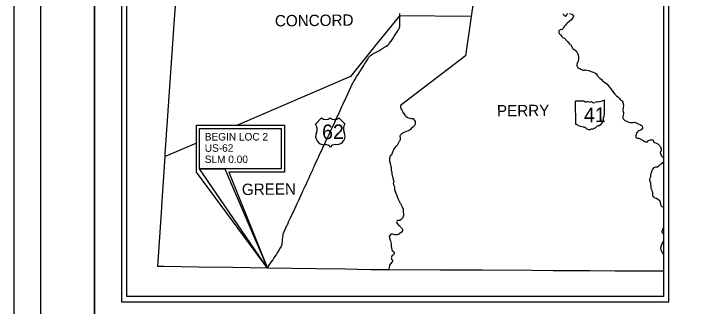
# Model space of a CAD drawing. Extents: x -12 to 164, y -741 to 24.
# Drawn here: x 0 to 12.93, y 8.83 to 14.26 of the extents above; entities that cross this region are included whole.
import ezdxf

# ---------------------------------------------------------------- set-up
doc = ezdxf.new("R2010")
doc.units = 0
for name, color, linetype in [('Default', 7, 'Continuous'), ('PM_P_Channelizing_Line', 7, 'Continuous'), ('PM_P_Crosswalk', 7, 'Continuous'), ('PM_P_Parking_Lot_Stall', 7, 'Continuous'), ('PM_P_Stop_Line', 7, 'Continuous'), ('PM_X_Channelizing_Line', 7, 'Continuous'), ('SH_Border', 7, 'Continuous'), ('SH_Cut_Line', 7, 'Continuous'), ('SH_Data', 7, 'Continuous'), ('SH_Text', 7, 'Continuous')]:
    doc.layers.add(name, color=color, linetype=linetype)

msp = doc.modelspace()

# ---------------------------------------------------------------- linework, layer by layer
at = {"layer": 'PM_P_Channelizing_Line'}
for points in [[(8.575, 14.773), (8.496, 14.218), (7.163, 14.227), (6.702, 13.656), (6.252, 13.102), (4.155, 12.192)], [(3.39, 11.861), (2.81, 11.609), (2.813, 11.659), (2.856, 12.282), (2.984, 14.169), (3.012, 14.574)], [(10.32, 14.274), (10.368, 14.258), (10.387, 14.246), (10.394, 14.237), (10.397, 14.23), (10.397, 14.22), (10.383, 14.193), (10.35, 14.151), (10.303, 14.109), (10.285, 14.096), (10.269, 14.078), (10.245, 14.054), (10.23, 14.036), (10.202, 13.99), (10.193, 13.981), (10.184, 13.975), (10.174, 13.972), (10.15, 13.969), (10.141, 13.964), (10.133, 13.957), (10.127, 13.948), (10.124, 13.939), (10.126, 13.931), (10.125, 13.921), (10.133, 13.903), (10.139, 13.895), (10.154, 13.878), (10.172, 13.853), (10.198, 13.825), (10.209, 13.817), (10.226, 13.813), (10.234, 13.808), (10.243, 13.8), (10.25, 13.791), (10.256, 13.782), (10.282, 13.757), (10.289, 13.748), (10.294, 13.74), (10.312, 13.724), (10.32, 13.707), (10.327, 13.698), (10.345, 13.692), (10.351, 13.682), (10.357, 13.656), (10.375, 13.631), (10.384, 13.622), (10.409, 13.6), (10.426, 13.587), (10.459, 13.553), (10.463, 13.545), (10.469, 13.536), (10.483, 13.504), (10.486, 13.495), (10.49, 13.477), (10.488, 13.431), (10.481, 13.393), (10.477, 13.368), (10.474, 13.36), (10.464, 13.341), (10.459, 13.324), (10.459, 13.316), (10.46, 13.299), (10.463, 13.29), (10.48, 13.264), (10.488, 13.257), (10.515, 13.246), (10.535, 13.237), (10.556, 13.225), (10.564, 13.222), (10.584, 13.219), (10.601, 13.22), (10.61, 13.223), (10.618, 13.223), (10.644, 13.219), (10.68, 13.211), (10.725, 13.195), (10.744, 13.186), (10.762, 13.181), (10.791, 13.17), (10.81, 13.157), (10.818, 13.149), (10.842, 13.112), (10.868, 13.085), (10.875, 13.076), (10.883, 13.069), (10.91, 13.049), (10.936, 13.022), (10.956, 13.007), (10.963, 12.999), (11.007, 12.967), (11.025, 12.951), (11.033, 12.943), (11.044, 12.925), (11.06, 12.907), (11.076, 12.891), (11.104, 12.849), (11.167, 12.772), (11.192, 12.746), (11.229, 12.716), (11.244, 12.698), (11.262, 12.673), (11.27, 12.664), (11.278, 12.659), (11.295, 12.655), (11.303, 12.648), (11.306, 12.641), (11.31, 12.625), (11.316, 12.616), (11.319, 12.608), (11.321, 12.599), (11.323, 12.555), (11.319, 12.529), (11.314, 12.476), (11.318, 12.449), (11.324, 12.432), (11.327, 12.415), (11.316, 12.345), (11.313, 12.335), (11.313, 12.327), (11.32, 12.31), (11.326, 12.303), (11.351, 12.283), (11.368, 12.272), (11.405, 12.258), (11.424, 12.253), (11.45, 12.247), (11.468, 12.244), (11.493, 12.243), (11.509, 12.244), (11.534, 12.249), (11.55, 12.245), (11.64, 12.203), (11.657, 12.191), (11.666, 12.184), (11.672, 12.175), (11.676, 12.166), (11.679, 12.149), (11.678, 12.141), (11.669, 12.123), (11.664, 12.115), (11.656, 12.106), (11.629, 12.098), (11.603, 12.086), (11.594, 12.079), (11.58, 12.062), (11.569, 12.043), (11.558, 12.018), (11.555, 12.01), (11.552, 11.993), (11.553, 11.977), (11.556, 11.969), (11.565, 11.961), (11.586, 11.954), (11.612, 11.951), (11.621, 11.947), (11.689, 11.912), (11.714, 11.892), (11.722, 11.888), (11.742, 11.882), (11.75, 11.881), (11.766, 11.882), (11.774, 11.886), (11.782, 11.903), (11.79, 11.91), (11.822, 11.92), (11.847, 11.921), (11.864, 11.92), (11.877, 11.914), (11.88, 11.905), (11.88, 11.897), (11.884, 11.889), (11.891, 11.879), (11.9, 11.874), (11.934, 11.862), (11.961, 11.847), (11.979, 11.83), (11.994, 11.814), (12.001, 11.806), (12.01, 11.789), (12.017, 11.772), (12.023, 11.754), (12.027, 11.729), (12.01, 11.701), (12.008, 11.693), (12.008, 11.684), (12.02, 11.648), (12.027, 11.631), (12.033, 11.622), (12.041, 11.614), (12.05, 11.608), (12.056, 11.601), (12.061, 11.593), (12.066, 11.581)], [(10.203, 14.265), (10.207, 14.255), (10.215, 14.243), (10.224, 14.234), (10.233, 14.226), (10.245, 14.22), (10.254, 14.221), (10.263, 14.23), (10.27, 14.247), (10.275, 14.255), (10.283, 14.264), (10.293, 14.273)], [(8.496, 14.218), (8.465, 13.997), (8.393, 13.483), (7.185, 12.558), (7.183, 12.543), (7.185, 12.526), (7.189, 12.509), (7.196, 12.491), (7.208, 12.471), (7.226, 12.434), (7.236, 12.417), (7.264, 12.381), (7.279, 12.364), (7.305, 12.342), (7.315, 12.337), (7.356, 12.325), (7.382, 12.32), (7.4, 12.319), (7.413, 12.316), (7.421, 12.311), (7.437, 12.293), (7.443, 12.284), (7.452, 12.264), (7.457, 12.244), (7.456, 12.227), (7.453, 12.21), (7.45, 12.201), (7.444, 12.191), (7.436, 12.183), (7.409, 12.16), (7.383, 12.132), (7.366, 12.111), (7.35, 12.099), (7.325, 12.089), (7.264, 12.066), (7.245, 12.055), (7.206, 12.035), (7.196, 12.028), (7.187, 12.019), (7.18, 12.01), (7.175, 12.001), (7.173, 11.992), (7.176, 11.956), (7.176, 11.923), (7.166, 11.897), (7.159, 11.889), (7.135, 11.844), (7.123, 11.816), (7.116, 11.807), (7.098, 11.799), (7.09, 11.793), (7.076, 11.775), (7.071, 11.767), (7.059, 11.745), (7.055, 11.734), (7.049, 11.724), (7.02, 11.656), (7.008, 11.639), (6.999, 11.63), (6.993, 11.62), (6.986, 11.601), (6.981, 11.565), (6.981, 11.53), (6.994, 11.464), (7.004, 11.423), (7.007, 11.404), (7.009, 11.37), (7.011, 11.361), (7.02, 11.309), (7.019, 11.284), (7.027, 11.257), (7.045, 11.199), (7.049, 11.179), (7.057, 11.152), (7.058, 11.143), (7.057, 11.134), (7.052, 11.125), (7.048, 11.116), (7.052, 11.092), (7.054, 11.084), (7.064, 11.057), (7.068, 11.049), (7.071, 11.04), (7.073, 11.023), (7.07, 11.005), (7.071, 10.997), (7.082, 10.963), (7.098, 10.929), (7.116, 10.886), (7.128, 10.849), (7.141, 10.819), (7.157, 10.783), (7.178, 10.743), (7.181, 10.735), (7.211, 10.676), (7.229, 10.633), (7.232, 10.615), (7.229, 10.587), (7.229, 10.577), (7.236, 10.544), (7.237, 10.525), (7.233, 10.497), (7.226, 10.479), (7.218, 10.465), (7.212, 10.457), (7.194, 10.438), (7.176, 10.426), (7.167, 10.423), (7.159, 10.421), (7.132, 10.419), (7.123, 10.414), (7.114, 10.406), (7.11, 10.396), (7.112, 10.38), (7.115, 10.372), (7.123, 10.362), (7.154, 10.328), (7.162, 10.32), (7.189, 10.299), (7.204, 10.283), (7.21, 10.275), (7.215, 10.267), (7.219, 10.257), (7.221, 10.237), (7.219, 10.227), (7.2, 10.201), (7.147, 10.158), (7.12, 10.152), (7.104, 10.152), (7.077, 10.154), (7.058, 10.159), (7.032, 10.168), (7.024, 10.169), (7.015, 10.168), (7.006, 10.164), (6.998, 10.158), (6.976, 10.131), (6.974, 10.123), (6.981, 10.097), (6.989, 10.062), (6.992, 10.054), (6.998, 10.045), (7.005, 10.019), (7.01, 9.983), (7.011, 9.936), (7.022, 9.881), (7.028, 9.865), (7.056, 9.836), (7.063, 9.818), (7.065, 9.809), (7.064, 9.801), (7.059, 9.793), (7.05, 9.784), (7.025, 9.767), (7.016, 9.75), (7.013, 9.737), (7.012, 9.728), (7.014, 9.712), (7.017, 9.703), (7.034, 9.677), (7.036, 9.667), (7.033, 9.659), (7.026, 9.649), (6.988, 9.606), (6.979, 9.588), (6.975, 9.577), (6.969, 9.55), (6.967, 9.513), (6.963, 9.503), (6.696, 9.505), (6.633, 9.506), (6.159, 9.513), (5.611, 9.521), (4.713, 9.535), (4.066, 9.545), (3.429, 9.554), (2.784, 9.564), (2.671, 9.566), (2.746, 10.664), (2.747, 10.685), (2.81, 11.609)], [(12.066, 10.665), (12.062, 10.667), (12.045, 10.676), (12.036, 10.683), (12.028, 10.692), (12.023, 10.701), (12.018, 10.726), (12.016, 10.75), (12.014, 10.759), (12.007, 10.777), (12.001, 10.786), (11.984, 10.801), (11.94, 10.829), (11.912, 10.837), (11.904, 10.84), (11.894, 10.846), (11.885, 10.855), (11.876, 10.872), (11.872, 10.879), (11.868, 10.907), (11.869, 10.925), (11.868, 10.942), (11.866, 10.952), (11.86, 10.972), (11.849, 10.997), (11.844, 11.005), (11.842, 11.014), (11.838, 11.04), (11.836, 11.107), (11.835, 11.115), (11.825, 11.132), (11.819, 11.151), (11.816, 11.168), (11.817, 11.184), (11.823, 11.21), (11.828, 11.226), (11.833, 11.235), (11.835, 11.243), (11.836, 11.26), (11.842, 11.297), (11.861, 11.352), (11.867, 11.365), (11.897, 11.404), (11.905, 11.411), (11.924, 11.417), (11.949, 11.419), (11.959, 11.422), (11.975, 11.432), (12.001, 11.455), (12.042, 11.48), (12.059, 11.497), (12.064, 11.505), (12.066, 11.508)], [(12.066, 10.173), (12.052, 10.185), (12.048, 10.194), (12.045, 10.203), (12.045, 10.219), (12.047, 10.227), (12.054, 10.254), (12.061, 10.275), (12.066, 10.284)], [(12.066, 9.796), (12.065, 9.796), (12.043, 9.83), (12.031, 9.856), (12.025, 9.872), (12.019, 9.899), (12.019, 9.915), (12.03, 9.958), (12.042, 9.992), (12.066, 10.045)], [(12.066, 9.477), (11.932, 9.477), (11.467, 9.48), (11.173, 9.481), (10.697, 9.484), (10.017, 9.487), (9.629, 9.489), (8.701, 9.494), (7.924, 9.498), (6.963, 9.503)]]:
    msp.add_lwpolyline(points, dxfattribs=at)
at = {"layer": 'PM_P_Crosswalk'}
msp.add_lwpolyline([(4.71, 9.536), (4.715, 9.546), (4.724, 9.559), (4.755, 9.606), (4.786, 9.651), (4.809, 9.685), (4.831, 9.717), (4.848, 9.742), (4.871, 9.776), (4.885, 9.798), (4.893, 9.811), (4.908, 9.837), (4.939, 9.891), (4.963, 9.933), (4.972, 9.949), (4.976, 9.958), (4.978, 9.963), (4.98, 9.968), (4.982, 9.976), (4.983, 9.983), (4.985, 9.993), (4.99, 10.042), (4.992, 10.065), (4.996, 10.103), (5, 10.144), (5.001, 10.157), (5.002, 10.165), (5.004, 10.175), (5.006, 10.182), (5.009, 10.189), (5.013, 10.199), (5.018, 10.21), (5.031, 10.238), (5.053, 10.285), (5.079, 10.34), (5.086, 10.354), (5.104, 10.394), (5.139, 10.468), (5.184, 10.564), (5.199, 10.596), (5.221, 10.643), (5.229, 10.661), (5.243, 10.692), (5.257, 10.722), (5.271, 10.752), (5.294, 10.801), (5.318, 10.855), (5.333, 10.888), (5.342, 10.907), (5.363, 10.953), (5.386, 11.002), (5.395, 11.023), (5.407, 11.049), (5.427, 11.093), (5.449, 11.14), (5.483, 11.215), (5.493, 11.236), (5.507, 11.266), (5.541, 11.341), (5.557, 11.376), (5.568, 11.402), (5.578, 11.423), (5.598, 11.467), (5.648, 11.574), (5.664, 11.609), (5.672, 11.628), (5.698, 11.684), (5.725, 11.742), (5.738, 11.77), (5.753, 11.803), (5.775, 11.85), (5.804, 11.913), (5.819, 11.945), (5.854, 12.022), (5.877, 12.071), (5.888, 12.094), (5.918, 12.16), (5.961, 12.253), (5.988, 12.311), (6.008, 12.353), (6.022, 12.383), (6.04, 12.423), (6.08, 12.509), (6.094, 12.54), (6.101, 12.554), (6.116, 12.589), (6.138, 12.635), (6.152, 12.665), (6.178, 12.721), (6.209, 12.789), (6.235, 12.845), (6.262, 12.903), (6.28, 12.943), (6.29, 12.964), (6.299, 12.982), (6.305, 12.993), (6.313, 13.007), (6.333, 13.039), (6.374, 13.105), (6.393, 13.135), (6.426, 13.188), (6.437, 13.205), (6.446, 13.22), (6.488, 13.288), (6.514, 13.329), (6.532, 13.357), (6.539, 13.368), (6.562, 13.405), (6.579, 13.434), (6.59, 13.451), (6.597, 13.462), (6.602, 13.468), (6.602, 13.468), (6.607, 13.474), (6.613, 13.479), (6.618, 13.484), (6.625, 13.489), (6.631, 13.493), (6.642, 13.5), (6.664, 13.513), (6.708, 13.539), (6.741, 13.558), (6.777, 13.579), (6.856, 13.626), (6.911, 13.659), (6.936, 13.674), (6.944, 13.679), (6.95, 13.684), (6.954, 13.687), (6.96, 13.693), (6.965, 13.698), (6.968, 13.702), (6.974, 13.711), (7.007, 13.76), (7.044, 13.816), (7.077, 13.868), (7.118, 13.93), (7.147, 13.973), (7.154, 13.984), (7.157, 13.99), (7.161, 13.997), (7.163, 14.005), (7.164, 14.007), (7.165, 14.01), (7.166, 14.015), (7.166, 14.016), (7.167, 14.02), (7.167, 14.027), (7.168, 14.048), (7.167, 14.066), (7.167, 14.094), (7.168, 14.138), (7.168, 14.169), (7.168, 14.226), (7.168, 14.236), (7.169, 14.259), (7.17, 14.274)], dxfattribs=at)
at = {"layer": 'PM_P_Parking_Lot_Stall'}
for p, q in [((10.428, 12.631), (10.432, 12.218)), ((10.593, 12.64), (10.434, 12.638)), ((10.975, 12.437), (10.973, 12.654)), ((10.975, 12.437), (10.975, 12.437))]:
    msp.add_line(p, q, dxfattribs=at)
for centre, radius, start, end in [((10.435, 12.632), 0.00631, 98.6686, 188.6686), ((10.631, 12.688), 0.0612, 232.1581, 271.6504), ((10.654, 12.408), 0.22, 81.0252, 95.5268), ((10.701, 12.637), 0.0177, 220.3306, 297.6409), ((10.728, 12.589), 0.0367, 55.0052, 119.6797), ((10.775, 12.655), 0.0442, 234.3948, 295.3667), ((10.854, 12.516), 0.116, 97.8847, 121.3074), ((10.774, 13.205), 0.578, 276.383, 289.445), ((10.967, 12.654), 0.00607, 352.4006, 98.2765), ((10.974, 12.421), 0.00939, 108.4825, 210.8755), ((10.969, 12.436), 0.00649, 290.1424, 8.2727), ((10.814, 12.318), 0.145, 292.8474, 9.5244), ((10.998, 12.347), 0.041, 137.345, 187.4681), ((10.914, 12.394), 0.0563, 340.5715, 24.1881), ((10.439, 12.217), 0.00637, 172.4969, 258.8452), ((10.439, 12.259), 0.0486, 267.8775, 281.1424), ((10.45, 12.194), 0.0175, 30.2869, 93.8103), ((10.667, 12.568), 0.417, 240.9515, 257.737), ((10.548, 12.033), 0.131, 47.7227, 76.3745), ((10.877, 12.106), 0.0791, 94.9417, 143.1153), ((10.688, 12.194), 0.0828, 231.2389, 286.8304), ((10.737, 12.052), 0.0681, 86.2337, 111.7485), ((10.742, 12.164), 0.0441, 269.3156, 316.0878), ((10.782, 12.124), 0.0124, 66.2903, 133.187), ((10.776, 12.181), 0.0467, 283.4117, 323.8157)]:
    msp.add_arc(centre, radius, start, end, dxfattribs=at)
at = {"layer": 'PM_P_Stop_Line'}
for p, q in [((5.717, 12.33), (5.605, 12.216)), ((6.15, 12.221), (6.035, 12.333)), ((5.767, 11.831), (5.79, 11.832)), ((5.972, 11.833), (5.994, 11.834))]:
    msp.add_line(p, q, dxfattribs=at)
for centre, radius, start, end in [((5.796, 12.412), 0.114, 226.1115, 314.9656), ((5.955, 12.414), 0.114, 226.1115, 314.9656), ((5.475, 12.123), 0.159, 335.0857, 35.5395), ((6.281, 12.131), 0.159, 145.5376, 205.9914), ((5.764, 11.99), 0.159, 155.3705, 271.1768), ((5.995, 11.992), 0.159, 269.9003, 25.7066), ((5.791, 11.718), 0.114, 37.4084, 90.5385), ((5.973, 11.72), 0.114, 90.5385, 143.6686)]:
    msp.add_arc(centre, radius, start, end, dxfattribs=at)
at = {"layer": 'SH_Border'}
for points in [[(0.5, 21.5), (1.5, 21.5), (1.5, 0.5), (0.5, 0.5)], [(1.5, 21.5), (33.5, 21.5), (33.5, 0.5), (1.5, 0.5)]]:
    msp.add_lwpolyline(points, close=True, dxfattribs=at)
at = {"layer": 'SH_Cut_Line'}
msp.add_lwpolyline([(0, 0), (34, 0), (34, 22), (0, 22)], close=True, dxfattribs=at)
at = {"layer": 'SH_Data'}
msp.add_line((2.1, 14.1), (2.1, 14.1), dxfattribs=at)
for points in [[(6.977, 21), (2, 21), (2, 8.906), (12.166, 8.906), (12.166, 18.656)], [(12.066, 18.656), (12.066, 9.006), (2.1, 9.006), (2.1, 20.9), (6.977, 20.9)]]:
    msp.add_lwpolyline(points, dxfattribs=at)
for points in [[(3.45, 12.132), (4.967, 12.132), (4.967, 11.381), (3.45, 11.381)], [(3.921, 11.381), (4.71, 9.536), (3.45, 11.381)]]:
    msp.add_lwpolyline(points, close=True, dxfattribs=at)
at = {"layer": 'SH_Text'}
for p, q in [((3.39, 12.192), (5.027, 12.192)), ((3.39, 11.321), (3.39, 12.192)), ((5.027, 12.192), (5.027, 11.321)), ((4.71, 9.536), (3.39, 11.321)), ((5.027, 11.321), (3.994, 11.321)), ((3.994, 11.321), (4.71, 9.536))]:
    msp.add_line(p, q, dxfattribs=at)

# ---------------------------------------------------------------- texts
at = {"layer": 'Default'}
for s, p in [('BEGIN LOC 2', (3.546, 11.909)), ('US-62', (3.546, 11.699)), ('SLM 0.00', (3.546, 11.489))]:
    msp.add_text(s, height=0.14, dxfattribs=at).set_placement(p)
at = {"layer": 'PM_P_Parking_Lot_Stall'}
msp.add_text('41', height=0.2724, rotation=0.5385, dxfattribs=at).set_placement((10.591, 12.248))
at = {"layer": 'PM_P_Stop_Line'}
msp.add_text('62', height=0.2724, rotation=0.5385, dxfattribs=at).set_placement((5.726, 11.933))
at = {"layer": 'PM_X_Channelizing_Line'}
for s, p in [('CONCORD', (4.85, 14.031)), ('PERRY', (8.975, 12.356)), ('GREEN', (4.236, 10.894))]:
    msp.add_text(s, height=0.2113, rotation=0.5386, dxfattribs=at).set_placement(p)

doc.saveas('drawing.dxf')
